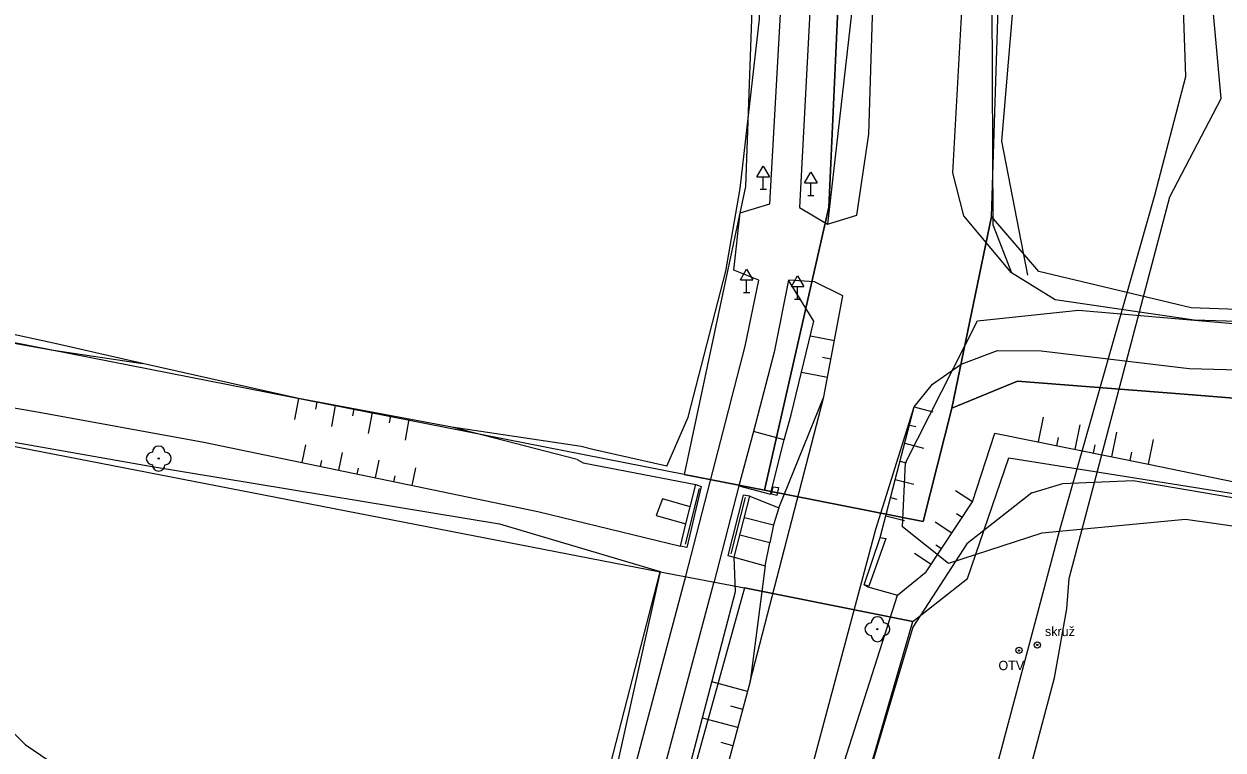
# Model space of a CAD drawing. Extents: x -555887 to -552101, y -1100251 to -1096546.
# Drawn here: x -554028.8 to -553932.8, y -1098361.9 to -1098303.8 of the extents above; entities that cross this region are included whole.
import ezdxf

# ---------------------------------------------------------------- set-up
doc = ezdxf.new("R2010")
doc.units = 0
for name, color, linetype in [('07_KANALIZACE', 7, 'Continuous'), ('07_VODOVOD', 7, 'Continuous'), ('PARCELY_silnice', 7, 'Continuous'), ('PARCELY_VHO', 7, 'Continuous'), ('vrstevnice', 7, 'Continuous'), ('ZSST', 7, 'Continuous')]:
    doc.layers.add(name, color=color, linetype=linetype)

msp = doc.modelspace()

# ---------------------------------------------------------------- linework, layer by layer
at = {"layer": '07_KANALIZACE'}
msp.add_lwpolyline([(-554087.209, -1098884.94), (-554044.091, -1098723.546), (-553946.28, -1098356.13), (-553945.28, -1098350.61), (-553945.106, -1098348.205), (-553937.04, -1098317.66), (-553932.95, -1098309.77), (-553933.89, -1098299.13), (-553960.89, -1098094.71)], dxfattribs=at)
at = {"layer": '07_VODOVOD'}
msp.add_lwpolyline([(-554079.661, -1098847.144), (-553997.696, -1098539.175), (-553945.85, -1098344.3), (-553938.248, -1098317.523), (-553935.78, -1098308.01), (-553936.175, -1098296.386), (-554003.21, -1097797.26)], dxfattribs=at)
at = {"layer": 'PARCELY_silnice'}
msp.add_lwpolyline([(-553997.67, -1098021.07), (-553963.01, -1098289.11), (-553964.35, -1098318.47), (-553969.49, -1098341.12), (-553956.79, -1098343.64), (-553954.49, -1098334.56), (-553951.31, -1098319.23), (-553950.34, -1098288.41), (-554001.81, -1097900.62)], dxfattribs=at)
for points in [[(-553975.92, -1098339.86), (-553969.49, -1098341.12), (-553964.35, -1098318.47), (-553963.01, -1098289.11), (-553997.67, -1098021.07), (-553998.62, -1098003.87), (-554000.89, -1097984.42), (-554003.33, -1097984.74), (-554002.07, -1097995.68), (-554004.77, -1098012.25), (-554004.64, -1098021.66), (-553970.02, -1098289.25), (-553971.01, -1098316.82)], [(-553954.49, -1098334.56), (-553949.24, -1098332.4), (-553935.89, -1098333.43), (-553913.06, -1098335.28), (-553883.16, -1098334.04), (-553867.22, -1098334.53), (-553855.57, -1098331.27), (-553837.55, -1098323.13), (-553842.59, -1098309.95), (-553846.87, -1098312.9), (-553850.11, -1098315.12), (-553858.85, -1098319.65), (-553869.99, -1098323.86), (-553884.06, -1098326.31), (-553912.66, -1098327.37), (-553935.34, -1098326.53), (-553947.54, -1098323.63), (-553951.31, -1098319.23)], [(-553977.83, -1098347.65), (-553971.09, -1098348.95), (-553988.06, -1098410.12), (-553994.13, -1098410.89)], [(-553988.06, -1098410.12), (-553991.282, -1098421.727), (-553987.992, -1098422.937), (-553982.15, -1098425.12), (-553979.24, -1098426.19), (-553957.61, -1098351.63), (-553971.09, -1098348.95)]]:
    msp.add_lwpolyline(points, close=True, dxfattribs=at)
at = {"layer": 'PARCELY_VHO'}
msp.add_lwpolyline([(-554187.71, -1098013.33), (-554186.2, -1098028.28), (-554148.41, -1098314.52), (-553977.83, -1098347.65), (-553971.09, -1098348.95), (-553957.61, -1098351.63), (-553953.24, -1098348.19), (-553949.93, -1098338.53), (-553911.81, -1098344.6), (-553827.63, -1098346.66), (-553837.55, -1098323.13), (-553855.57, -1098331.27), (-553867.22, -1098334.53), (-553883.16, -1098334.04), (-553913.06, -1098335.28), (-553935.89, -1098333.43), (-553949.24, -1098332.4), (-553954.49, -1098334.56), (-553956.79, -1098343.64), (-553969.49, -1098341.12), (-553975.92, -1098339.86), (-554126.54, -1098310.27), (-554135.62, -1098304.48), (-554178.28, -1098027.18)], close=True, dxfattribs=at)
at = {"layer": 'vrstevnice'}
for points in [[(-554031.026, -1098298.897), (-554035.452, -1098307.125), (-554039.309, -1098315.099), (-554043.291, -1098327.541), (-554043.87, -1098338.123), (-554041.542, -1098346.28), (-554037.622, -1098352.542), (-554028.673, -1098361.478), (-554017.894, -1098368.808), (-554010.495, -1098373.386), (-554005.187, -1098376.518), (-554000.845, -1098380.051), (-553995.729, -1098385.745), (-553989.99, -1098393.779), (-553986.558, -1098402.488), (-553975.316, -1098410.837), (-553964.711, -1098418.402), (-553944.61, -1098429.395), (-553930.532, -1098442.245)], [(-553915.963, -1098346.269), (-553935.795, -1098343.458), (-553947.302, -1098344.558), (-553954.769, -1098347.003), (-553958.442, -1098344.069), (-553958.197, -1098338.935), (-553952.443, -1098327.567), (-553944.364, -1098326.711), (-553917.432, -1098329.034)]]:
    msp.add_lwpolyline(points, dxfattribs=at)
at = {"layer": 'ZSST'}
for p, q in [((-553962.53, -1098302.98), (-553964.45, -1098319.83)), ((-553970.09, -1098316.04), (-553969.59, -1098315.19)), ((-553969.59, -1098315.19), (-553969.09, -1098316.04)), ((-553970.09, -1098316.04), (-553969.09, -1098316.04)), ((-553969.59, -1098317.04), (-553969.59, -1098316.04)), ((-553966.28, -1098316.53), (-553965.78, -1098315.68)), ((-553965.78, -1098315.68), (-553965.28, -1098316.53)), ((-553969.84, -1098317.04), (-553969.34, -1098317.04)), ((-553966.28, -1098316.53), (-553965.28, -1098316.53)), ((-553965.78, -1098317.53), (-553965.78, -1098316.53)), ((-553966.03, -1098317.53), (-553965.53, -1098317.53)), ((-553951.2, -1098319.93), (-553949.72, -1098323.72)), ((-553971.42, -1098324.3), (-553970.92, -1098323.45)), ((-553970.92, -1098323.45), (-553970.42, -1098324.3)), ((-553967.34, -1098324.83), (-553966.84, -1098323.98)), ((-553966.84, -1098323.98), (-553966.34, -1098324.83)), ((-553971.42, -1098324.3), (-553970.42, -1098324.3)), ((-553970.92, -1098325.3), (-553970.92, -1098324.3)), ((-553967.34, -1098324.83), (-553966.34, -1098324.83)), ((-553966.84, -1098325.83), (-553966.84, -1098324.83)), ((-553971.17, -1098325.3), (-553970.67, -1098325.3)), ((-553967.09, -1098325.83), (-553966.59, -1098325.83)), ((-553964.75, -1098333.66), (-553963.21, -1098325.57)), ((-553963.893, -1098329.16), (-553965.818, -1098328.794)), ((-553964.174, -1098330.634), (-553964.84, -1098330.507)), ((-553964.454, -1098332.107), (-553966.528, -1098331.712)), ((-553970.63, -1098356.44), (-553964.75, -1098333.66)), ((-553968.33, -1098342.54), (-553964.75, -1098333.66)), ((-554006.79, -1098333.8), (-554007.103, -1098335.48)), ((-554005.315, -1098334.075), (-554005.42, -1098334.634)), ((-554003.841, -1098334.35), (-554004.154, -1098336.03)), ((-554002.366, -1098334.624), (-554002.47, -1098335.184)), ((-553960.24, -1098344.91), (-553957.5, -1098334.46)), ((-553957.5, -1098334.46), (-553956.006, -1098334.852)), ((-554000.892, -1098334.899), (-554001.205, -1098336.579)), ((-553999.417, -1098335.174), (-553999.521, -1098335.733)), ((-553997.942, -1098335.449), (-553998.255, -1098337.129)), ((-553947.571, -1098337.266), (-553947.171, -1098335.288)), ((-553984.49, -1098338.66), (-553994.5, -1098336.09)), ((-553957.88, -1098335.911), (-553957.383, -1098336.041)), ((-553944.631, -1098337.86), (-553944.231, -1098335.883)), ((-553941.69, -1098338.455), (-553941.29, -1098336.478)), ((-554006.491, -1098338.92), (-554006.197, -1098337.503)), ((-553958.261, -1098337.362), (-553956.767, -1098337.754)), ((-553946.101, -1098337.563), (-553945.968, -1098336.904)), ((-553943.161, -1098338.158), (-553943.027, -1098337.499)), ((-553938.75, -1098339.05), (-553938.35, -1098337.072)), ((-554003.554, -1098339.529), (-554003.26, -1098338.113)), ((-553940.22, -1098338.753), (-553940.087, -1098338.094)), ((-554005.022, -1098339.225), (-554004.925, -1098338.753)), ((-554002.085, -1098339.834), (-554001.987, -1098339.362)), ((-554000.616, -1098340.139), (-554000.322, -1098338.722)), ((-553997.679, -1098340.748), (-553997.385, -1098339.331)), ((-553958.641, -1098338.813), (-553958.144, -1098338.943)), ((-553999.147, -1098340.443), (-553999.05, -1098339.971)), ((-553959.022, -1098340.264), (-553957.528, -1098340.656)), ((-553974.73, -1098340.99), (-553975.85, -1098345.45)), ((-553952.85, -1098342.07), (-553954.19, -1098341.187)), ((-553971.04, -1098341.7), (-553972.18, -1098346.22)), ((-553970.67, -1098341.61), (-553968.33, -1098342.54)), ((-553959.402, -1098341.715), (-553958.905, -1098341.845)), ((-553968.33, -1098342.54), (-553968.76, -1098343.89)), ((-553959.783, -1098343.166), (-553958.289, -1098343.557)), ((-553953.675, -1098343.323), (-553954.122, -1098343.028)), ((-553968.76, -1098343.89), (-553968.76, -1098343.89)), ((-553954.501, -1098344.575), (-553955.841, -1098343.692)), ((-553959.79, -1098345), (-553959.79, -1098345)), ((-553969.44, -1098347.17), (-553969.06, -1098345.34)), ((-553955.326, -1098345.828), (-553955.772, -1098345.533)), ((-553971.82, -1098349.22), (-553971.92, -1098346.49)), ((-553971.92, -1098346.49), (-553969.44, -1098347.17)), ((-553956.151, -1098347.08), (-553957.492, -1098346.197)), ((-553969.44, -1098347.17), (-553970.63, -1098356.44)), ((-553961.13, -1098348.81), (-553961.13, -1098348.81)), ((-553965.33, -1098369.81), (-553958.85, -1098349.53)), ((-553970.842, -1098357.229), (-553973.705, -1098356.457)), ((-553971.233, -1098358.677), (-553972.182, -1098358.421)), ((-553971.623, -1098360.125), (-553974.461, -1098359.361)), ((-553972.013, -1098361.574), (-553972.954, -1098361.32))]:
    msp.add_line(p, q, dxfattribs=at)
for points in [[(-553977.31, -1098339.19), (-553975.61, -1098335.29), (-553972.59, -1098323.6), (-553971.44, -1098316.97), (-553969.88, -1098303.44), (-553969.81, -1098290.61), (-553972.17, -1098269.21), (-553975.16, -1098246.95), (-553978.59, -1098220.4), (-553983.45, -1098184.31), (-553986.7, -1098159.44), (-553989.55, -1098137.24), (-553994, -1098104), (-554000.05, -1098057.93), (-554004.75, -1098020.85), (-554005.01, -1098018.62), (-554004.8, -1098012.3), (-554004.6, -1098001.9), (-554004.55, -1097991.77)], [(-553951.2, -1098319.93), (-553951.28, -1098302.07), (-553958.7, -1098233.53), (-553961.27, -1098215.25), (-553968.42, -1098161.7), (-553973.37, -1098125.99), (-553977.56, -1098092.07), (-553983.59, -1098047.63), (-553987.39, -1098018.59), (-553990.78, -1097993.85)], [(-553988.71, -1097993.49), (-553985.58, -1098018.09), (-553981.87, -1098047.25), (-553975.9, -1098091.95), (-553971.51, -1098125.49), (-553966.51, -1098161.83), (-553959.93, -1098205.07), (-553958.71, -1098213.37), (-553956.01, -1098234), (-553950.44, -1098275.83), (-553949.64, -1098302.75), (-553950.51, -1098313.18), (-553948.45, -1098323.92)], [(-554178.25, -1098049.48), (-554173.19, -1098075.27), (-554169.22, -1098108.72), (-554164.87, -1098138.62), (-554160.6, -1098167.78), (-554156.82, -1098196.15), (-554154.08, -1098222.79), (-554149.57, -1098251.11), (-554145.47, -1098278.08), (-554140.24, -1098303.52), (-554135.08, -1098307.75), (-554132.08, -1098310.77), (-554125.76, -1098312.67), (-554120.31, -1098313.42), (-554102.66, -1098315.91), (-554080.42, -1098320.1), (-554045.01, -1098326.59), (-554026.42, -1098329.93), (-554026.4, -1098329.91), (-554019.26, -1098330.99)], [(-553981.91, -1098371.05), (-553975.78, -1098348), (-553971.03, -1098329.61), (-553969.94, -1098324.32), (-553971.94, -1098323.51), (-553971.44, -1098318.93), (-553969.06, -1098318.21), (-553968.22, -1098303.02), (-553968.41, -1098291.14), (-553970.99, -1098268.85), (-553973.86, -1098246.72), (-553977.39, -1098220.02), (-553982.05, -1098183.91), (-553985.32, -1098159.26), (-553988.25, -1098137.18)], [(-553962.11, -1098319.11), (-553961.13, -1098312.64), (-553960.67, -1098297.16), (-553962.58, -1098275.13), (-553965.7, -1098250.39), (-553969.37, -1098222.81), (-553974.36, -1098184.73), (-553978.58, -1098152.8)], [(-553983.11, -1098159.04), (-553979.8, -1098183.68), (-553975.13, -1098219.88), (-553971.62, -1098246.33), (-553968.77, -1098268.62), (-553966.14, -1098291.12), (-553965.87, -1098302.84), (-553966.69, -1098318.51), (-553964.45, -1098319.83), (-553962.11, -1098319.11)], [(-554019.26, -1098330.99), (-554026.15, -1098329.41), (-554044.34, -1098325.47), (-554074.7, -1098319.7), (-554101.86, -1098314.93), (-554119.69, -1098311.26), (-554131.89, -1098305.66), (-554136.04, -1098299.66), (-554138.73, -1098279.38), (-554143.31, -1098249.22), (-554148.32, -1098221.15), (-554152.46, -1098196.01), (-554156.99, -1098165.3)], [(-553883.71, -1098327.25), (-553914.68, -1098328.15), (-553935.1, -1098327.52), (-553946.22, -1098325.88), (-553949.72, -1098323.72), (-553953.54, -1098319.18), (-553954.42, -1098315.73), (-553953.71, -1098303.24), (-553954.34, -1098287.84), (-553957.61, -1098261.59)], [(-554145.09, -1098310.61), (-554143.95, -1098312.32), (-554132.6, -1098315.26), (-554100.6, -1098322.27), (-554084.58, -1098324.03), (-554060.09, -1098328.46), (-554044.59, -1098331.97), (-554027.83, -1098334.82), (-554014.35, -1098337.29), (-553987.64, -1098342.83), (-553976.21, -1098345.61)], [(-554148.86, -1098314.99), (-554114.15, -1098321.64), (-554085.61, -1098327.06), (-554061.07, -1098330.97), (-554040.28, -1098335.39), (-554018.66, -1098339.2), (-553990.69, -1098343.82), (-553977.83, -1098347.63), (-553982.98, -1098370.76), (-553989.63, -1098395.32), (-553995.97, -1098411.98), (-553997.32, -1098415.17), (-553997.6, -1098419.21)], [(-553963.21, -1098325.57), (-553965.49, -1098324.45), (-553967.56, -1098324.31), (-553968.72, -1098330.07), (-553970.38, -1098336.42), (-553971.55, -1098340.77), (-553973.54, -1098348.54)], [(-553967.91, -1098337.09), (-553967.35, -1098335.09), (-553965.53, -1098327.61), (-553967.56, -1098324.31)], [(-553960.59, -1098344.24), (-553957.5, -1098334.46), (-553956.04, -1098332.65), (-553953.76, -1098331.03), (-553950.84, -1098329.95), (-553947.35, -1098329.98), (-553935.49, -1098331.39), (-553914.72, -1098331.94), (-553882.8, -1098331.23)], [(-553994.5, -1098336.09), (-554006.79, -1098333.8), (-554019.26, -1098330.99)], [(-553977.31, -1098339.19), (-553983.22, -1098337.87), (-553984.15, -1098337.63), (-553994.5, -1098336.09)], [(-553971.55, -1098340.77), (-553969, -1098341.43), (-553967.91, -1098337.09), (-553970.38, -1098336.42)], [(-553961.51, -1098348.7), (-553961.21, -1098348.85), (-553958.85, -1098349.53), (-553956.54, -1098347.67), (-553952.85, -1098342.07), (-553951.06, -1098336.56), (-553938.75, -1098339.05), (-553922.33, -1098342.42), (-553906.16, -1098343.41), (-553899.53, -1098343.91), (-553894.07, -1098350.54)], [(-553984.49, -1098338.66), (-553984, -1098338.94), (-553974.98, -1098340.67)], [(-553948.1, -1098341.33), (-553945.61, -1098340.58), (-553939.98, -1098340.36), (-553922.17, -1098343.38), (-553910.39, -1098346.11), (-553901.19, -1098350.57), (-553888.19, -1098356.26), (-553881.99, -1098355.61), (-553854.47, -1098348.27)], [(-553948.1, -1098341.33), (-553953.3, -1098345.41), (-553957.62, -1098352.08), (-553963.11, -1098370.53), (-553973.59, -1098408.79), (-553975.59, -1098417.34)], [(-553975.44, -1098342.45), (-553977.65, -1098341.82), (-553978.15, -1098343.14), (-553975.78, -1098343.83)], [(-553971.09, -1098343.3), (-553968.76, -1098343.89), (-553969.06, -1098345.34), (-553971.46, -1098344.73)], [(-554054.81, -1098696.59), (-554053.95, -1098693.56), (-554052.78, -1098689.01), (-554042.99, -1098652.55), (-554033.29, -1098616.71), (-554022.44, -1098576.81), (-554007.03, -1098518.73), (-553997.47, -1098483.19), (-553987.92, -1098447.16), (-553980.78, -1098420.44), (-553979.49, -1098415.59), (-553977.44, -1098407.81), (-553973.16, -1098391.31), (-553969.69, -1098378.4), (-553965.21, -1098361.58), (-553960.59, -1098344.24)], [(-553986.08, -1098413.77), (-553990.68, -1098412.81), (-553986.26, -1098396.14), (-553979.73, -1098371.75), (-553973.54, -1098348.54)], [(-553990.68, -1098412.81), (-553987.67, -1098410.1), (-553983.47, -1098393.76), (-553983.35, -1098389.1), (-553981.39, -1098385.06), (-553978.34, -1098374.25), (-553971.82, -1098349.22)], [(-553970.63, -1098356.44), (-553978.69, -1098386.36), (-553981.17, -1098395.61), (-553984.64, -1098408.69), (-553986.08, -1098413.77)]]:
    msp.add_lwpolyline(points, dxfattribs=at)
for points in [[(-553974.98, -1098340.67), (-553974.55, -1098340.83), (-553975.71, -1098345.72), (-553976.21, -1098345.61), (-553975.78, -1098343.83), (-553975.44, -1098342.45)], [(-553968.94, -1098341.43), (-553968.79, -1098340.85), (-553968.37, -1098340.91), (-553968.49, -1098341.54)], [(-553971.2, -1098341.51), (-553972.42, -1098346.34), (-553971.92, -1098346.49), (-553970.67, -1098341.61)], [(-553960.24, -1098344.91), (-553959.79, -1098345), (-553961.13, -1098348.81), (-553961.51, -1098348.7)]]:
    msp.add_lwpolyline(points, close=True, dxfattribs=at)
for centre, radius in [((-554017.97, -1098338.59), 0.05), ((-553960.45, -1098352.25), 0.05), ((-553949.12, -1098353.95), 0.25), ((-553947.66, -1098353.51), 0.25), ((-553947.66, -1098353.51), 0.05), ((-553949.12, -1098353.95), 0.05)]:
    msp.add_circle(centre, radius, dxfattribs=at)
for centre, start, end in [((-554018.47, -1098338.59), 90, 270), ((-554017.97, -1098338.09), 0, 180), ((-554017.47, -1098338.59), 270, 90), ((-554017.97, -1098339.09), 180, 0), ((-553960.95, -1098352.25), 90, 270), ((-553960.45, -1098351.75), 0, 180), ((-553959.95, -1098352.25), 270, 90), ((-553960.45, -1098352.75), 180, 0)]:
    msp.add_arc(centre, 0.5, start, end, dxfattribs=at)

# ---------------------------------------------------------------- texts
for s, p in [('skruž', (-553947.041, -1098352.8)), ('OTV', (-553950.764, -1098355.527))]:
    msp.add_text(s, height=0.75, dxfattribs=at).set_placement(p)

doc.saveas('drawing.dxf')
